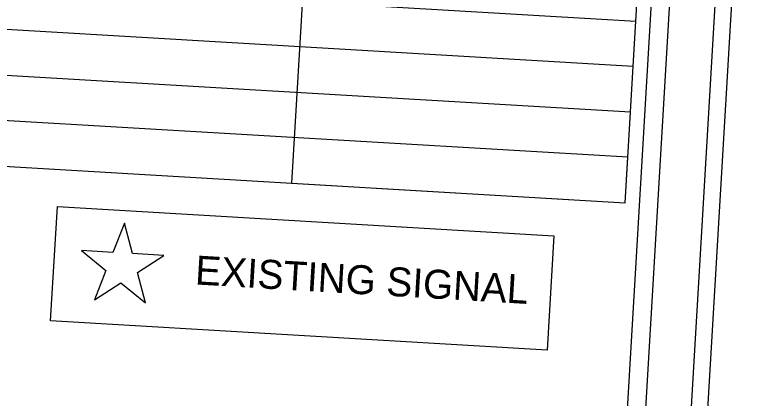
# Model space of a CAD drawing. Extents: x 1998567 to 2027801, y 439108 to 451079.
# Drawn here: x 2019178 to 2021220, y 447730 to 448783 of the extents above; entities that cross this region are included whole.
import ezdxf

# ---------------------------------------------------------------- set-up
doc = ezdxf.new("R2010")
doc.units = 0
for name, color, linetype in [('Prop DSN Text', 7, 'Continuous'), ('Prop Grid Mask', 7, 'Continuous'), ('Prop RDY Traffic Signal CELL', 7, 'Continuous'), ('Sheet Plot Border Inside CELL', 7, 'Continuous'), ('Sheet Plot Border Outside CELL', 7, 'Continuous'), ('Sheet Title CELL', 7, 'Continuous')]:
    doc.layers.add(name, color=color, linetype=linetype)

msp = doc.modelspace()

# ---------------------------------------------------------------- linework, layer by layer
at = {"layer": 'Prop Grid Mask'}
msp.add_lwpolyline([(2019294.1, 448256.7), (2020657, 448176.4), (2020638.4, 447862.2), (2019275.5, 447942.6)], close=True, dxfattribs=at)
at = {"layer": 'Prop RDY Traffic Signal CELL'}
msp.add_lwpolyline([(2019446.7, 448130.4), (2019360.4, 448135.5), (2019427.3, 448080.7), (2019395.7, 447999.9), (2019468.7, 448046.7), (2019535.7, 447991.7), (2019513.8, 448075.5), (2019586.7, 448122.2), (2019500.2, 448127.3), (2019478.3, 448211.2), (2019446.7, 448130.4)], dxfattribs=at)
at = {"layer": 'Sheet Plot Border Inside CELL'}
msp.add_lwpolyline([(2003905.2, 440314.9), (2020541.3, 439334.2), (2021162.2, 449866.9), (2004526.1, 450847.6)], close=True, dxfattribs=at)
at = {"layer": 'Sheet Plot Border Outside CELL'}
msp.add_lwpolyline([(2021220.3, 450088.4), (2004409.5, 451079.4), (2003762.2, 440098.6), (2020573, 439107.6)], close=True, dxfattribs=at)
at = {"layer": 'Sheet Title CELL'}
for points in [[(2020003.3, 449444), (2019937.1, 448321), (2020852.5, 448267), (2020940.8, 449764.4)], [(2020423.9, 439467), (2021030, 449749)], [(2020485.8, 441366.5), (2020977.2, 449702.2)], [(2018136.7, 448928), (2020881.9, 448766.2), (2020889.3, 448890.9)], [(2018107.3, 448428.9), (2020852.5, 448267), (2020859.8, 448391.7), (2018114.6, 448553.6), (2018122, 448678.3), (2020867.2, 448516.5), (2020874.6, 448641.2), (2018129.4, 448803.1)]]:
    msp.add_lwpolyline(points, dxfattribs=at)

# ---------------------------------------------------------------- texts
at = {"layer": 'Prop DSN Text'}
msp.add_text('EXISTING SIGNAL', height=79.498, rotation=356.6264, dxfattribs=at).set_placement((2019670.7, 448042.7))

doc.saveas('drawing.dxf')
